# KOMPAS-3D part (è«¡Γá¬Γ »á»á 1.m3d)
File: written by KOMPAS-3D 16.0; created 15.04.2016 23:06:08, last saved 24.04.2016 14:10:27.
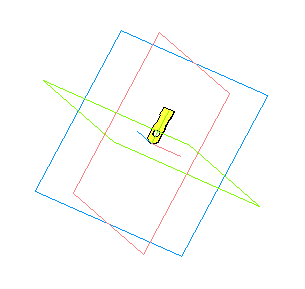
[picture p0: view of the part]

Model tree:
1. Эскиз:1
2. Операция выдавливания:1
     Расстояние 1 = 0.3
3. Фаска:1
     Угол = 45; Длина 1 = 1; Длина 2 = 1
4. Эскиз:2
5. Операция выдавливания:2
     Расстояние 1 = 0.5
6. Эскиз:3
7. Вырезать элемент выдавливания:1
     Расстояние 1 = 10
